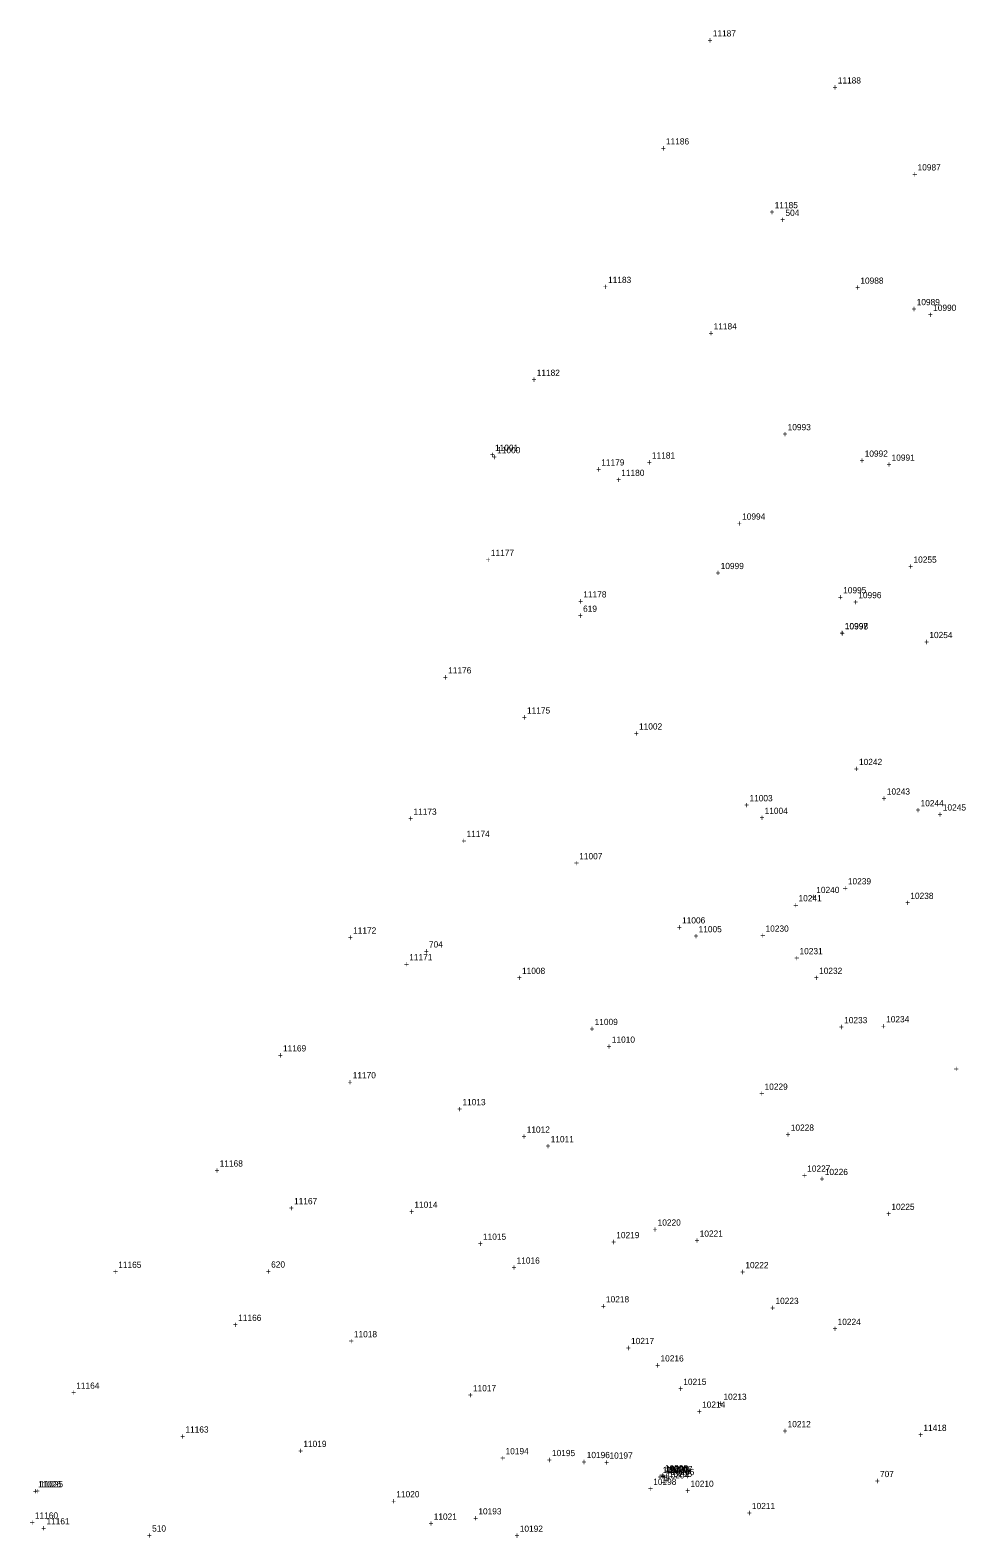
# Model space of a CAD drawing. Extents: x 1160051 to 1162814, y 614604 to 619560.
# Drawn here: x 1160353 to 1160725, y 615845 to 616450 of the extents above; entities that cross this region are included whole.
import ezdxf

# ---------------------------------------------------------------- set-up
doc = ezdxf.new("R2010")
doc.units = 0
for name, color, linetype in [('S_Control_Temp_Traverse', 7, 'Continuous'), ('S_Control_Traverse_Point', 7, 'Continuous'), ('S_Drainage_Culvert_Top', 7, 'Continuous'), ('S_Drainage_Invert', 7, 'Continuous'), ('S_Ground_Elevation', 7, 'Continuous'), ('S_Traffic_Sign_DoublePost', 7, 'Continuous'), ('S_Trees_TreeLine', 7, 'Continuous')]:
    doc.layers.add(name, color=color, linetype=linetype)

msp = doc.modelspace()

# ---------------------------------------------------------------- texts
at = {"layer": 'S_Control_Temp_Traverse'}
for s, p in [('619', (1160574.65, 616216.62)), ('+', (1160572.59, 616213.87)), ('+', (1160447.45, 615950.75)), ('620', (1160449.51, 615953.5))]:
    msp.add_text(s, height=2.5, dxfattribs=at).set_placement(p)
at = {"layer": 'S_Control_Traverse_Point'}
for s, p in [('504', (1160655.84, 616375.46)), ('504', (1160655.84, 616375.46)), ('504', (1160655.84, 616375.46)), ('504', (1160655.84, 616375.46)), ('+', (1160653.78, 616372.71)), ('+', (1160653.78, 616372.71)), ('+', (1160653.78, 616372.71)), ('+', (1160653.78, 616372.71)), ('+', (1160510.76, 616079.18)), ('+', (1160510.76, 616079.18)), ('704', (1160512.82, 616081.93)), ('704', (1160512.82, 616081.93)), ('+', (1160691.71, 615866.69)), ('+', (1160691.71, 615866.69)), ('+', (1160691.71, 615866.69)), ('+', (1160691.71, 615866.69)), ('+', (1160691.71, 615866.69)), ('+', (1160691.71, 615866.69)), ('+', (1160691.71, 615866.69)), ('+', (1160691.71, 615866.69)), ('+', (1160691.71, 615866.69)), ('+', (1160691.71, 615866.69)), ('+', (1160691.71, 615866.69)), ('+', (1160691.71, 615866.69)), ('707', (1160693.77, 615869.44)), ('707', (1160693.77, 615869.44)), ('707', (1160693.77, 615869.44)), ('707', (1160693.77, 615869.44)), ('707', (1160693.77, 615869.44)), ('707', (1160693.77, 615869.44)), ('707', (1160693.77, 615869.44)), ('707', (1160693.77, 615869.44)), ('707', (1160693.77, 615869.44)), ('707', (1160693.77, 615869.44)), ('707', (1160693.77, 615869.44)), ('707', (1160693.77, 615869.44)), ('510', (1160401.76, 615847.58)), ('510', (1160401.76, 615847.58)), ('510', (1160401.76, 615847.58)), ('510', (1160401.76, 615847.58)), ('510', (1160401.76, 615847.58)), ('510', (1160401.76, 615847.58)), ('510', (1160401.76, 615847.58)), ('+', (1160399.69, 615844.83)), ('+', (1160399.69, 615844.83)), ('+', (1160399.69, 615844.83)), ('+', (1160399.69, 615844.83)), ('+', (1160399.69, 615844.83)), ('+', (1160399.69, 615844.83)), ('+', (1160399.69, 615844.83))]:
    msp.add_text(s, height=2.5, dxfattribs=at).set_placement(p)
at = {"layer": 'S_Drainage_Culvert_Top'}
for s, p in [('+', (1160538.12, 616277.48)), ('11000', (1160540.18, 616280.23)), ('+', (1160677.65, 616206.78)), ('10998', (1160679.71, 616209.53)), ('10201', (1160607.8, 615871.1)), ('11025', (1160356.72, 615865.37)), ('+', (1160605.74, 615868.35)), ('+', (1160354.66, 615862.62))]:
    msp.add_text(s, height=2.5, dxfattribs=at).set_placement(p)
at = {"layer": 'S_Drainage_Invert'}
for s, p in [('+', (1160537.27, 616278.43)), ('11001', (1160539.33, 616281.18)), ('+', (1160677.58, 616206.91)), ('10997', (1160679.65, 616209.66)), ('10200', (1160607.81, 615871.43)), ('11026', (1160355.99, 615865.32)), ('+', (1160605.75, 615868.68)), ('+', (1160353.93, 615862.57))]:
    msp.add_text(s, height=2.5, dxfattribs=at).set_placement(p)
at = {"layer": 'S_Ground_Elevation'}
for s, p in [('11187', (1160626.69, 616447.45)), ('+', (1160624.63, 616444.7)), ('11188', (1160676.84, 616428.58)), ('+', (1160674.78, 616425.83)), ('11186', (1160607.91, 616404.12)), ('+', (1160605.85, 616401.37)), ('10987', (1160708.85, 616393.69)), ('+', (1160706.79, 616390.94)), ('+', (1160649.47, 616375.78)), ('11185', (1160651.53, 616378.53)), ('+', (1160582.62, 616345.79)), ('11183', (1160584.68, 616348.54)), ('+', (1160683.84, 616345.48)), ('10988', (1160685.9, 616348.23)), ('10989', (1160708.5, 616339.64)), ('10990', (1160715.1, 616337.34)), ('+', (1160706.44, 616336.89)), ('+', (1160713.04, 616334.59)), ('+', (1160624.98, 616327.16)), ('11184', (1160627.04, 616329.91)), ('+', (1160553.99, 616308.53)), ('11182', (1160556.05, 616311.28)), ('10993', (1160656.73, 616289.46)), ('+', (1160654.67, 616286.71)), ('11181', (1160602.28, 616278.12)), ('10992', (1160687.64, 616278.84)), ('10991', (1160698.43, 616277.22)), ('+', (1160600.22, 616275.37)), ('+', (1160685.57, 616276.09)), ('+', (1160696.37, 616274.47)), ('10994', (1160638.46, 616253.59)), ('+', (1160636.4, 616250.84)), ('+', (1160535.59, 616236.26)), ('11177', (1160537.65, 616239.01)), ('10255', (1160707.22, 616236.31)), ('+', (1160627.8, 616231)), ('10999', (1160629.86, 616233.75)), ('+', (1160705.16, 616233.56)), ('11178', (1160574.75, 616222.37)), ('10995', (1160679, 616224.02)), ('10996', (1160685.07, 616222.07)), ('+', (1160572.69, 616219.62)), ('+', (1160676.94, 616221.27)), ('+', (1160683, 616219.32)), ('10254', (1160713.58, 616206.06)), ('+', (1160711.51, 616203.31)), ('11176', (1160520.53, 616191.88)), ('+', (1160518.47, 616189.13)), ('11175', (1160552.17, 616175.81)), ('+', (1160550.1, 616173.06)), ('11002', (1160597.1, 616169.38)), ('+', (1160595.04, 616166.63)), ('+', (1160683.3, 616152.38)), ('10242', (1160685.36, 616155.13)), ('10243', (1160696.52, 616143.28)), ('+', (1160639.35, 616137.84)), ('11003', (1160641.41, 616140.59)), ('+', (1160694.46, 616140.53)), ('10244', (1160710.07, 616138.59)), ('+', (1160504.55, 616132.44)), ('11173', (1160506.61, 616135.19)), ('+', (1160645.44, 616132.76)), ('11004', (1160647.5, 616135.51)), ('+', (1160708.01, 616135.84)), ('11174', (1160527.91, 616126.25)), ('+', (1160525.85, 616123.5)), ('+', (1160571.05, 616114.57)), ('11007', (1160573.11, 616117.32)), ('10239', (1160680.89, 616107.25)), ('10240', (1160668.21, 616103.77)), ('+', (1160678.83, 616104.5)), ('10238', (1160705.95, 616101.41)), ('+', (1160659.03, 616097.7)), ('10241', (1160661.09, 616100.45)), ('+', (1160666.15, 616101.02)), ('+', (1160703.89, 616098.66)), ('11006', (1160614.37, 616091.58)), ('+', (1160480.33, 616084.76)), ('11172', (1160482.39, 616087.51)), ('+', (1160612.31, 616088.83)), ('+', (1160618.96, 616085.29)), ('11005', (1160621.02, 616088.04)), ('+', (1160645.8, 616085.51)), ('10230', (1160647.86, 616088.26)), ('11171', (1160504.9, 616076.78)), ('10231', (1160661.49, 616079.23)), ('+', (1160502.84, 616074.03)), ('11008', (1160550.16, 616071.31)), ('+', (1160659.43, 616076.48)), ('10232', (1160669.35, 616071.35)), ('+', (1160548.1, 616068.56)), ('+', (1160667.29, 616068.6)), ('+', (1160577.23, 616048.06)), ('11009', (1160579.29, 616050.81)), ('+', (1160677.33, 616048.81)), ('10233', (1160679.39, 616051.56)), ('+', (1160694.18, 616049.16)), ('10234', (1160696.24, 616051.91)), ('+', (1160584.12, 616040.97)), ('11010', (1160586.19, 616043.72)), ('+', (1160452.21, 616037.47)), ('11169', (1160454.27, 616040.22)), ('11170', (1160482.24, 616029.44)), ('+', (1160723.36, 616032.02)), ('+', (1160480.18, 616026.69)), ('10229', (1160647.46, 616024.85)), ('11013', (1160526.25, 616018.65)), ('+', (1160645.4, 616022.1)), ('+', (1160524.19, 616015.9)), ('+', (1160549.98, 616004.87)), ('11012', (1160552.04, 616007.62)), ('+', (1160655.93, 616005.66)), ('10228', (1160657.99, 616008.41)), ('+', (1160559.59, 616001.03)), ('11011', (1160561.66, 616003.78)), ('11168', (1160428.86, 615994.04)), ('+', (1160426.8, 615991.29)), ('+', (1160662.51, 615989.22)), ('10227', (1160664.57, 615991.97)), ('+', (1160669.56, 615987.88)), ('10226', (1160671.62, 615990.63)), ('+', (1160456.64, 615976.18)), ('11167', (1160458.7, 615978.93)), ('+', (1160504.9, 615974.74)), ('11014', (1160506.96, 615977.49)), ('10225', (1160698.35, 615976.65)), ('10220', (1160604.57, 615970.33)), ('+', (1160696.29, 615973.9)), ('11015', (1160534.5, 615964.66)), ('+', (1160585.91, 615962.55)), ('10219', (1160587.97, 615965.3)), ('+', (1160602.51, 615967.58)), ('+', (1160619.38, 615963.14)), ('10221', (1160621.44, 615965.89)), ('+', (1160532.44, 615961.91)), ('+', (1160386.09, 615950.64)), ('11165', (1160388.16, 615953.39)), ('+', (1160545.93, 615952.34)), ('11016', (1160547.99, 615955.09)), ('+', (1160637.7, 615950.52)), ('10222', (1160639.76, 615953.27)), ('10218', (1160583.84, 615939.54)), ('10223', (1160651.84, 615938.89)), ('11166', (1160436.28, 615932.12)), ('+', (1160581.78, 615936.79)), ('+', (1160649.78, 615936.14)), ('+', (1160434.21, 615929.37)), ('11018', (1160482.7, 615925.55)), ('+', (1160674.71, 615927.75)), ('10224', (1160676.77, 615930.5)), ('+', (1160480.64, 615922.8)), ('+', (1160591.83, 615920.05)), ('10217', (1160593.89, 615922.8)), ('10216', (1160605.71, 615915.83)), ('+', (1160603.65, 615913.08)), ('+', (1160369.25, 615902.14)), ('11164', (1160371.32, 615904.89)), ('11017', (1160530.47, 615903.87)), ('+', (1160612.8, 615903.7)), ('10215', (1160614.86, 615906.45)), ('+', (1160528.41, 615901.12)), ('+', (1160628.91, 615897.7)), ('10213', (1160630.97, 615900.45)), ('10212', (1160656.71, 615889.47)), ('+', (1160413.05, 615884.55)), ('11163', (1160415.11, 615887.3)), ('+', (1160654.64, 615886.72)), ('+', (1160709.13, 615885.22)), ('11418', (1160711.19, 615887.97)), ('+', (1160460.37, 615878.77)), ('11019', (1160462.43, 615881.52)), ('10194', (1160543.55, 615878.62)), ('10195', (1160562.18, 615877.86)), ('10196', (1160576.12, 615877.06)), ('+', (1160541.49, 615875.87)), ('+', (1160560.12, 615875.11)), ('+', (1160574.06, 615874.31)), ('+', (1160583.19, 615874.09)), ('10197', (1160585.25, 615876.84)), ('10199', (1160606.59, 615871.04)), ('10208', (1160607.48, 615871.81)), ('10207', (1160609.27, 615871.38)), ('10198', (1160602.79, 615866.32)), ('+', (1160604.53, 615868.29)), ('+', (1160605.41, 615869.06)), ('+', (1160605.82, 615866.15)), ('+', (1160606.24, 615868.19)), ('+', (1160607.01, 615866.76)), ('+', (1160607.2, 615868.63)), ('+', (1160607.92, 615867.5)), ('10204', (1160607.88, 615868.9)), ('10209', (1160608.3, 615870.94)), ('10205', (1160609.07, 615869.51)), ('10206', (1160609.98, 615870.25)), ('10210', (1160617.75, 615865.53)), ('11020', (1160499.73, 615861.33)), ('+', (1160600.73, 615863.57)), ('+', (1160615.69, 615862.78)), ('+', (1160497.67, 615858.58)), ('10193', (1160532.64, 615854.47)), ('+', (1160640.34, 615853.85)), ('10211', (1160642.4, 615856.6)), ('+', (1160352.66, 615850.03)), ('11160', (1160354.72, 615852.78)), ('+', (1160357.3, 615847.72)), ('11161', (1160359.36, 615850.47)), ('+', (1160512.67, 615849.6)), ('11021', (1160514.73, 615852.35)), ('+', (1160530.57, 615851.73)), ('10192', (1160549.25, 615847.5)), ('+', (1160547.19, 615844.75))]:
    msp.add_text(s, height=2.5, dxfattribs=at).set_placement(p)
at = {"layer": 'S_Traffic_Sign_DoublePost'}
for s, p in [('+', (1160579.9, 616272.56)), ('11179', (1160581.96, 616275.31)), ('11180', (1160589.97, 616271.13)), ('+', (1160587.91, 616268.38))]:
    msp.add_text(s, height=2.5, dxfattribs=at).set_placement(p)
at = {"layer": 'S_Trees_TreeLine'}
for s, p in [('+', (1160716.93, 616134.13)), ('10245', (1160718.99, 616136.88)), ('10214', (1160622.41, 615897.27)), ('+', (1160620.35, 615894.52))]:
    msp.add_text(s, height=2.5, dxfattribs=at).set_placement(p)

doc.saveas('drawing.dxf')
